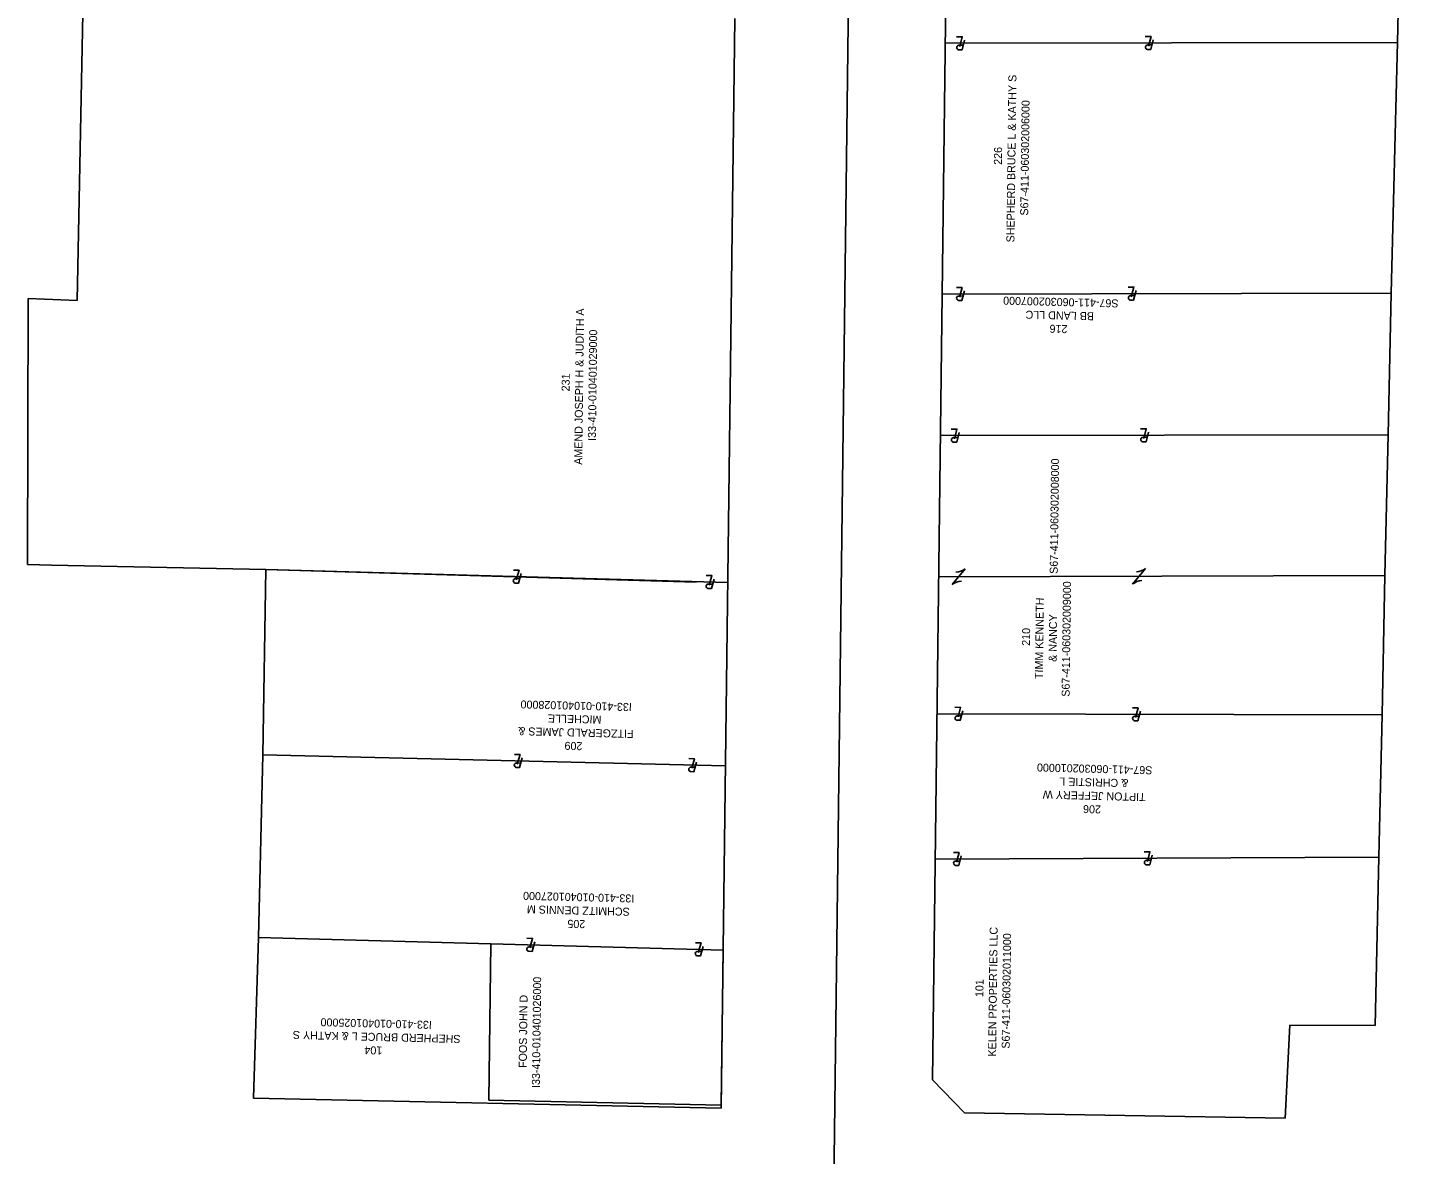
# Model space of a CAD drawing. Extents: x 1652206 to 1653153, y 604222 to 614600.
# Drawn here: x 1652307.5 to 1652731.4, y 607280.6 to 607628 of the extents above; entities that cross this region are included whole.
import ezdxf

# ---------------------------------------------------------------- set-up
doc = ezdxf.new("R2010")
doc.units = 0
for name, color, linetype in [('_CIVIL_CONSTRUCTION', 7, 'Continuous'), ('GE_P_Alignment', 7, 'Continuous'), ('GE_P_Alignment_100_Bearings', 7, 'Continuous'), ('GE_P_Alignment_100_Cardinal_Points', 7, 'Continuous'), ('GE_P_Alignment_100_Distances', 7, 'Continuous')]:
    doc.layers.add(name, color=color, linetype=linetype)

msp = doc.modelspace()

# ---------------------------------------------------------------- linework, layer by layer
at = {"layer": '_CIVIL_CONSTRUCTION'}
msp.add_line((1652550.86, 606872.07), (1652575.14, 608815.48), dxfattribs=at)
at = {"layer": 'GE_P_Alignment'}
for p, q in [((1652449.64, 607297.35), (1652450.22, 607345.57)), ((1652450.22, 607345.57), (1652521.75, 607343.66)), ((1652521.75, 607343.66), (1652521.15, 607295.83)), ((1652521.15, 607295.83), (1652449.64, 607297.35))]:
    msp.add_line(p, q, dxfattribs=at)
at = {"layer": 'GE_P_Alignment_100_Bearings'}
for p, q in [((1652731.35, 607705.9), (1652729.47, 607623.32)), ((1652322.74, 607543.82), (1652325, 607655.62)), ((1652729.47, 607623.32), (1652590.24, 607623.1)), ((1652595.72, 607622.48), (1652594.42, 607622.48)), ((1652594.92, 607623.1), (1652594.92, 607623.1)), ((1652653.86, 607622.58), (1652652.56, 607622.57)), ((1652653.06, 607623.2), (1652653.06, 607623.2)), ((1652729.47, 607623.32), (1652727.59, 607546.12)), ((1652307.5, 607462.45), (1652307.74, 607544.44)), ((1652307.74, 607544.44), (1652322.74, 607543.82)), ((1652727.59, 607546.12), (1652589.28, 607545.82)), ((1652595.68, 607545.22), (1652594.39, 607545.21)), ((1652594.88, 607545.84), (1652594.88, 607545.84)), ((1652648.58, 607545.33), (1652647.28, 607545.33)), ((1652647.78, 607545.95), (1652647.78, 607545.95)), ((1652727.59, 607546.12), (1652726.61, 607502.45)), ((1652726.61, 607502.45), (1652588.73, 607502.18)), ((1652594.07, 607501.57), (1652592.78, 607501.57)), ((1652593.27, 607502.19), (1652593.27, 607502.19)), ((1652652.41, 607501.68), (1652651.12, 607501.68)), ((1652651.61, 607502.3), (1652651.61, 607502.3)), ((1652726.61, 607502.45), (1652725.61, 607459.04)), ((1652314.86, 607462.25), (1652307.5, 607462.45)), ((1652380.86, 607460.89), (1652314.86, 607462.25)), ((1652379.98, 607403.83), (1652380.86, 607460.89)), ((1652380.86, 607460.89), (1652523.16, 607456.9)), ((1652513.42, 607457.02), (1652380.86, 607460.89)), ((1652459.13, 607458.07), (1652457.84, 607458.11)), ((1652458.35, 607458.72), (1652458.35, 607458.72)), ((1652725.61, 607459.04), (1652588.19, 607458.72)), ((1652596.33, 607461.14), (1652592.34, 607456.33)), ((1652594.33, 607458.73), (1652594.33, 607458.73)), ((1652651.9, 607461.27), (1652647.91, 607456.46)), ((1652649.9, 607458.86), (1652649.9, 607458.86)), ((1652725.61, 607459.04), (1652724.75, 607416.15)), ((1652518.55, 607456.41), (1652517.25, 607456.44)), ((1652517.76, 607457.05), (1652517.76, 607457.05)), ((1652724.75, 607416.15), (1652587.66, 607416.47)), ((1652595.21, 607415.83), (1652593.91, 607415.83)), ((1652594.41, 607416.46), (1652594.41, 607416.46)), ((1652649.88, 607415.7), (1652648.58, 607415.7)), ((1652649.08, 607416.33), (1652649.08, 607416.33)), ((1652724.75, 607416.15), (1652723.75, 607372.25)), ((1652378.6, 607347.57), (1652379.98, 607403.83)), ((1652379.98, 607403.83), (1652522.46, 607400.38)), ((1652522.46, 607400.38), (1652379.98, 607403.83)), ((1652459.45, 607401.28), (1652458.15, 607401.31)), ((1652458.66, 607401.92), (1652458.66, 607401.92)), ((1652513.17, 607399.98), (1652511.87, 607400.02)), ((1652512.38, 607400.63), (1652512.38, 607400.63)), ((1652587.1, 607371.69), (1652723.75, 607372.25)), ((1652594.74, 607371.09), (1652593.44, 607371.09)), ((1652593.94, 607371.72), (1652593.94, 607371.72)), ((1652653.53, 607371.34), (1652652.23, 607371.33)), ((1652652.73, 607371.96), (1652652.73, 607371.96)), ((1652723.75, 607372.25), (1652722.61, 607320.45)), ((1652377.06, 607297.99), (1652378.6, 607347.57)), ((1652378.6, 607347.57), (1652450.22, 607345.57)), ((1652450.22, 607345.57), (1652378.6, 607347.57)), ((1652450.22, 607345.57), (1652449.64, 607297.35)), ((1652521.75, 607343.66), (1652450.22, 607345.57)), ((1652463.31, 607344.59), (1652462.01, 607344.63)), ((1652462.52, 607345.24), (1652462.52, 607345.24)), ((1652514.4, 607343.86), (1652514.4, 607343.86)), ((1652515.19, 607343.21), (1652513.89, 607343.25)), ((1652696.35, 607320.49), (1652694.91, 607291.81)), ((1652722.61, 607320.45), (1652696.35, 607320.49))]:
    msp.add_line(p, q, dxfattribs=at)
for points in [[(1652594.65, 607622.14), (1652595.44, 607625.1), (1652593.69, 607625.1)], [(1652596.14, 607624.07), (1652595.36, 607621.11), (1652594.33, 607621.11)], [(1652652.79, 607622.24), (1652653.58, 607625.2), (1652651.83, 607625.19)], [(1652654.28, 607624.17), (1652653.5, 607621.2), (1652652.47, 607621.2)], [(1652594.62, 607544.88), (1652595.4, 607547.83), (1652593.65, 607547.83)], [(1652647.51, 607544.99), (1652648.3, 607547.95), (1652646.55, 607547.95)], [(1652596.1, 607546.81), (1652595.32, 607543.84), (1652594.29, 607543.84)], [(1652649, 607546.92), (1652648.22, 607543.96), (1652647.19, 607543.96)], [(1652593.01, 607501.23), (1652593.79, 607504.19), (1652592.05, 607504.18)], [(1652594.49, 607503.16), (1652593.72, 607500.19), (1652592.68, 607500.19)], [(1652651.35, 607501.34), (1652652.13, 607504.3), (1652650.39, 607504.3)], [(1652652.83, 607503.27), (1652652.06, 607500.31), (1652651.02, 607500.31)], [(1652458.06, 607457.76), (1652458.93, 607460.7), (1652457.18, 607460.75)], [(1652459.6, 607459.65), (1652458.73, 607456.71), (1652457.7, 607456.74)], [(1652517.47, 607456.1), (1652518.34, 607459.04), (1652516.6, 607459.08)], [(1652519.01, 607457.99), (1652518.15, 607455.05), (1652517.12, 607455.08)], [(1652594.14, 607415.5), (1652594.94, 607418.45), (1652593.19, 607418.46)], [(1652595.63, 607417.42), (1652594.84, 607414.46), (1652593.81, 607414.46)], [(1652648.81, 607415.37), (1652649.61, 607418.32), (1652647.86, 607418.33)], [(1652650.3, 607417.29), (1652649.51, 607414.33), (1652648.48, 607414.33)], [(1652458.37, 607400.97), (1652459.23, 607403.91), (1652457.49, 607403.95)], [(1652459.91, 607402.86), (1652459.05, 607399.92), (1652458.02, 607399.94)], [(1652512.09, 607399.67), (1652512.95, 607402.61), (1652511.21, 607402.65)], [(1652513.62, 607401.57), (1652512.77, 607398.62), (1652511.74, 607398.65)], [(1652593.67, 607370.75), (1652594.45, 607373.71), (1652592.71, 607373.71)], [(1652652.46, 607370.99), (1652653.24, 607373.95), (1652651.5, 607373.95)], [(1652595.15, 607372.69), (1652594.38, 607369.72), (1652593.35, 607369.72)], [(1652653.94, 607372.93), (1652653.17, 607369.96), (1652652.14, 607369.96)], [(1652462.23, 607344.29), (1652463.1, 607347.22), (1652461.35, 607347.27)], [(1652463.77, 607346.17), (1652462.91, 607343.23), (1652461.88, 607343.26)], [(1652514.11, 607342.91), (1652514.98, 607345.84), (1652513.23, 607345.89)], [(1652515.65, 607344.79), (1652514.79, 607341.85), (1652513.76, 607341.88)]]:
    msp.add_lwpolyline(points, dxfattribs=at)
for centre, radius, start, end in [((1652594.43, 607621.79), 0.69, 90.5653, 261.4224), ((1652652.57, 607621.89), 0.69, 90.5653, 261.4224), ((1652594.39, 607544.52), 0.69, 90.5953, 261.4524), ((1652647.29, 607544.64), 0.69, 90.5953, 261.4524), ((1652592.78, 607500.88), 0.69, 90.5808, 261.4379), ((1652651.12, 607500.99), 0.69, 90.5808, 261.4379), ((1652457.82, 607457.42), 0.69, 88.8681, 259.7252), ((1652593.15, 607465.43), 5.34, 273.8313, 306.4739), ((1652648.73, 607465.56), 5.34, 273.8313, 306.4739), ((1652517.24, 607455.76), 0.69, 88.8681, 259.7252), ((1652595.51, 607452.04), 5.34, 93.8313, 126.4739), ((1652651.08, 607452.17), 5.34, 93.8313, 126.4739), ((1652593.91, 607415.14), 0.69, 90.3344, 261.1915), ((1652648.59, 607415.01), 0.69, 90.3344, 261.1915), ((1652458.14, 607400.62), 0.69, 89.087, 259.9441), ((1652511.86, 607399.33), 0.69, 89.087, 259.9441), ((1652593.45, 607370.4), 0.69, 90.7049, 261.562), ((1652652.24, 607370.64), 0.69, 90.7049, 261.562), ((1652462, 607343.94), 0.69, 88.9473, 259.8044), ((1652513.88, 607342.56), 0.69, 88.9473, 259.8044)]:
    msp.add_arc(centre, radius, start, end, dxfattribs=at)
at = {"layer": 'GE_P_Alignment_100_Distances'}
for p, q in [((1652586.25, 607303.66), (1652590.57, 607649.43)), ((1652521.14, 607294.92), (1652525.33, 607630.72)), ((1652596.13, 607293.49), (1652586.25, 607303.66)), ((1652521.14, 607294.92), (1652377.06, 607297.99)), ((1652694.91, 607291.81), (1652596.13, 607293.49))]:
    msp.add_line(p, q, dxfattribs=at)

# ---------------------------------------------------------------- texts
at = {"layer": 'GE_P_Alignment_100_Cardinal_Points'}
for s, height, rotation, p in [('SHEPHERD BRUCE L & KATHY S', 2.4653, 89.2843, (1652611.49, 607561.72)), ('S67-411-060302006000', 2.4653, 89.2843, (1652615.75, 607569.99)), ('226', 2.465, 89.2843, (1652607.64, 607585.63)), ('S67-411-060302007000', 2.4653, 178.565, (1652643.61, 607544.14)), ('AMEND JOSEPH H & JUDITH A', 2.4653, 89.2843, (1652478.35, 607493.19)), ('BB LAND LLC', 2.4653, 178.565, (1652636.04, 607540.18)), ('I33-410-010401029000', 2.4653, 89.2843, (1652482.57, 607500.56)), ('216', 2.465, 178.565, (1652627.87, 607536.23)), ('231', 2.465, 89.2843, (1652474.48, 607515.81)), ('S67-411-060302008000', 2.4653, 89.2843, (1652624.84, 607459.57)), ('S67-411-060302009000', 2.4653, 89.2843, (1652628.51, 607421.71)), ('TIMM KENNETH', 2.4653, 89.2843, (1652620.27, 607427.16)), ('& NANCY', 2.465, 89.2843, (1652624.49, 607432.47)), ('210', 2.465, 89.2843, (1652616.29, 607437.4)), ('I33-410-010401028000', 2.4653, 178.565, (1652493.68, 607419.74)), ('MICHELLE', 2.465, 178.565, (1652484.31, 607415.86)), ('FITZGERALD JAMES & ', 2.4653, 178.565, (1652494.2, 607411.46)), ('209', 2.465, 178.565, (1652478.46, 607407.7)), ('S67-411-060302010000', 2.4653, 178.565, (1652654.04, 607400.27)), ('& CHRISTIE L', 2.4653, 178.565, (1652646.62, 607396.3)), ('TIPTON JEFFERY W ', 2.4653, 178.565, (1652651.95, 607392.01)), ('206', 2.465, 178.565, (1652638.19, 607388.21)), ('I33-410-010401027000', 2.4653, 178.565, (1652494.45, 607360.75)), ('SCHMITZ DENNIS M', 2.4653, 178.565, (1652493.04, 607356.66)), ('205', 2.465, 178.565, (1652479.34, 607352.85)), ('KELEN PROPERTIES LLC', 2.4653, 89.2843, (1652605.85, 607310.82)), ('S67-411-060302011000', 2.4653, 89.2843, (1652610.04, 607313.25)), ('I33-410-010401026000', 2.4653, 89.2843, (1652465.31, 607301.13)), ('101', 2.465, 89.2843, (1652601.93, 607329.14)), ('FOOS JOHN D', 2.4653, 89.2843, (1652461.27, 607307.3)), ('I33-410-010401025000', 2.4653, 178.565, (1652432.07, 607321.8)), ('SHEPHERD BRUCE L & KATHY S', 2.4653, 178.565, (1652440.91, 607317.45)), ('104', 2.465, 178.565, (1652416.81, 607313.9))]:
    msp.add_text(s, height=height, rotation=rotation, dxfattribs=at).set_placement(p)

doc.saveas('drawing.dxf')
